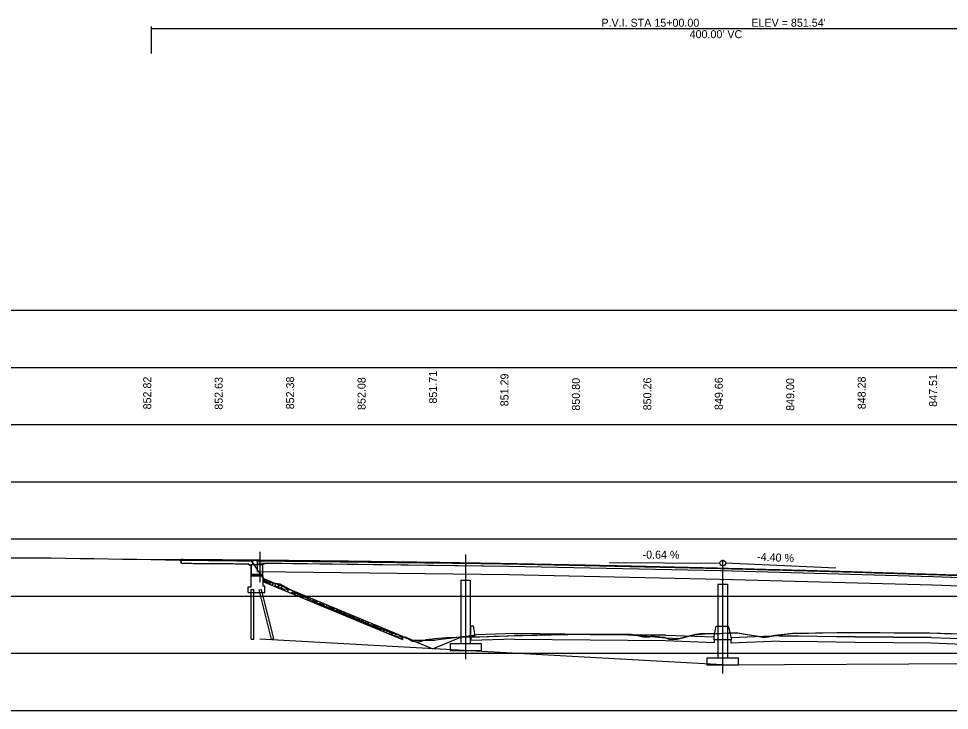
# Model space of a CAD drawing. Extents: x -434 to 1339, y -871 to 603.
# Drawn here: x 253.6 to 579.3, y -500 to -257.9 of the extents above; entities that cross this region are included whole.
import ezdxf

# ---------------------------------------------------------------- set-up
doc = ezdxf.new("R2010")
doc.units = 0
for name, color, linetype in [('BR_P_Brg_Pad_Object', 7, 'Continuous'), ('BR_P_Gen_Approach_Slab', 7, 'Continuous'), ('BR_P_Gen_Hatch', 7, 'Continuous'), ('BR_P_Gen_Slope_Protection', 7, 'Continuous'), ('BR_P_Slab_Object', 7, 'Continuous'), ('BR_P_Sub_Const_Joint', 7, 'Continuous'), ('BR_P_Sub_Object', 7, 'Continuous'), ('BR_X_Beam_Object', 7, 'Continuous'), ('BR_X_Sub_Centerline', 7, 'Continuous'), ('BR_X_Sub_Deep_Hidden', 7, 'Continuous'), ('BR_X_Sub_Deep_Object', 7, 'Continuous'), ('BR_X_Sub_Object', 7, 'Continuous'), ('GK_Cells', 7, 'Continuous'), ('PF_P_Grade_Line', 7, 'Continuous'), ('PF_P_Text', 7, 'Continuous'), ('PF_X_Ground_Line', 7, 'Continuous'), ('PV_P_EOP', 7, 'Continuous'), ('SC_Scratch1', 7, 'Continuous'), ('SC_Scratch2', 7, 'Continuous'), ('XS_P_Barrier', 7, 'Continuous'), ('XS_P_Barrier_Surface', 7, 'Continuous'), ('XS_P_Ditch_Bottom', 7, 'Continuous'), ('XS_P_Finished_Grade', 7, 'Continuous'), ('XS_P_Finished_Grade_Seeded', 7, 'Continuous'), ('XS_P_Pavt_Surface', 7, 'Continuous'), ('XS_P_Shoulder_Surface', 7, 'Continuous'), ('XS_P_Subgrade', 7, 'Continuous'), ('XS_X_Ground_Line', 7, 'Continuous')]:
    doc.layers.add(name, color=color, linetype=linetype)

msp = doc.modelspace()

# ---------------------------------------------------------------- linework, layer by layer
at = {"layer": 'BR_P_Brg_Pad_Object'}
msp.add_lwpolyline([(337.49, -452.29), (338.49, -452.29), (338.49, -452.46), (337.49, -452.46)], close=True, dxfattribs=at)
at = {"layer": 'BR_P_Gen_Approach_Slab'}
for p, q in [((310.5, -448.51), (310.5, -447.25)), ((334.45, -449.18), (333.98, -448.71)), ((334.45, -449.18), (334.95, -449.18))]:
    msp.add_line(p, q, dxfattribs=at)
msp.add_open_spline([(310.5, -448.51), (318.33, -448.57), (326.16, -448.63), (333.98, -448.71)], degree=2, dxfattribs=at)
at = {"layer": 'BR_P_Gen_Hatch'}
for p, q in [((310.5, -447.25), (310.5, -448.51)), ((333.98, -448.71), (334.45, -449.18)), ((334.45, -449.18), (334.95, -449.18)), ((334.95, -449.18), (334.95, -452.96)), ((339.09, -448.97), (340.09, -448.44)), ((339.09, -452.96), (339.09, -448.97)), ((334.95, -452.96), (339.09, -452.96))]:
    msp.add_line(p, q, dxfattribs=at)
for points in [[(340.09, -448.44), (425.16, -449.49), (499.17, -451.07), (573.52, -453.13), (641.6, -455.57)], [(339.36, -453.9), (339.09, -453.93)], [(339.31, -454.82), (339.23, -454.34), (339.53, -454), (339.6, -454)], [(340.15, -454.23), (340.26, -454.36), (340.23, -454.72), (339.89, -455.01), (339.6, -455.01), (339.31, -454.82)], [(340.11, -455.3), (340.27, -454.94), (340.64, -454.63), (340.95, -454.62), (341.22, -454.9), (341.29, -455.46), (341.2, -455.75)], [(341.58, -455.91), (341.52, -455.57), (341.82, -455.23), (342.27, -455.24), (342.55, -455.59), (342.52, -455.95), (342.25, -456.18)], [(344.59, -456.07), (344.5, -456.33), (344.15, -456.7), (343.81, -456.75), (343.5, -456.49), (343.41, -456.07), (343.45, -455.73)], [(343.44, -455.76), (343.5, -455.62)], [(344.63, -457.06), (344.54, -456.58), (344.84, -456.25), (345.01, -456.25)], [(345.42, -456.42), (345.58, -456.61), (345.54, -456.96), (345.21, -457.25), (344.92, -457.26), (344.63, -457.06)], [(345.23, -457.42), (345.63, -457.33), (345.96, -457.37)], [(345.94, -457.37), (346.46, -457.59), (346.77, -457.96), (346.77, -458.06)], [(347.09, -457.51), (347.02, -457.08)], [(347.95, -457.47), (347.68, -457.7), (347.39, -457.7), (347.09, -457.51)], [(348.06, -458.6), (347.86, -458.4), (347.8, -458.06), (348.07, -457.75), (348.44, -457.67)], [(349.46, -458.1), (349.63, -458.29), (349.63, -458.6), (349.35, -458.88), (348.87, -458.93)], [(349.44, -459.17), (349.53, -459.07), (349.97, -459.08), (350.26, -459.43), (350.25, -459.51)], [(351.11, -458.78), (351.08, -458.88), (350.73, -459.24), (350.38, -459.3), (350.08, -459.03), (349.99, -458.62), (350.02, -458.33)], [(351.06, -459.84), (351.1, -459.73), (351.47, -459.41), (351.79, -459.41), (352.06, -459.69), (352.13, -460.25), (352.12, -460.28)], [(352.39, -460.15), (352.31, -459.67), (352.56, -459.38)], [(353.34, -459.71), (353.31, -460.05), (352.97, -460.34), (352.68, -460.35), (352.39, -460.15)], [(353.13, -460.7), (353.11, -460.61), (353.38, -460.31), (353.79, -460.22), (354.13, -460.25)], [(354.11, -460.25), (354.62, -460.47), (354.93, -460.84), (354.94, -461.16), (354.73, -461.36)], [(355.36, -461.63), (355.38, -461.41)], [(355.37, -461.43), (355.6, -460.91), (355.81, -460.73)], [(356.58, -461.05), (356.62, -461.43), (356.43, -462), (356.39, -462.05)], [(356.63, -462.16), (356.58, -461.87), (356.76, -461.67), (357.03, -461.67), (357.2, -461.88), (357.18, -462.1), (356.98, -462.27), (356.91, -462.27)], [(356.64, -462.16), (356.63, -462.16)], [(358.09, -461.68), (357.89, -461.88), (357.55, -461.94), (357.25, -461.67), (357.16, -461.29)], [(358.19, -462.51), (358.1, -462.03), (358.33, -461.78)], [(359.13, -462.11), (359.1, -462.41), (358.77, -462.7), (358.48, -462.7), (358.19, -462.51)], [(359.48, -462.8), (359.4, -462.32), (359.46, -462.25)], [(358.75, -463.04), (358.89, -462.88), (359.16, -462.89), (359.33, -463.1), (359.32, -463.27)], [(360.41, -462.64), (360.4, -462.7), (360.07, -462.99), (359.78, -462.99), (359.48, -462.8)], [(359.52, -463.36), (359.76, -463.35), (359.93, -463.52)], [(360.51, -463.45), (360.43, -462.97), (360.64, -462.74)], [(361.46, -463.08), (361.43, -463.36), (361.1, -463.65), (360.81, -463.65), (360.51, -463.45)], [(360.96, -463.95), (361, -463.9), (361.42, -463.81), (361.75, -463.85)], [(361.73, -463.84), (362.25, -464.07), (362.56, -464.44), (362.56, -464.62)], [(363.67, -464), (363.64, -464.03), (363.08, -464.1), (362.51, -463.91), (362.14, -463.56), (362.11, -463.35)], [(362.87, -464.74), (362.85, -464.67), (363.15, -464.34), (363.6, -464.35), (363.89, -464.7), (363.85, -465.06), (363.78, -465.12)], [(363.93, -464.34), (363.88, -464.08)], [(363.92, -465.18), (364.04, -465.06), (364.3, -465.06), (364.48, -465.27), (364.46, -465.41)], [(364.44, -464.31), (364.27, -464.45), (364.1, -464.46), (363.93, -464.34)], [(364.83, -464.91), (364.78, -464.62), (364.88, -464.5)], [(364.8, -465.55), (365.02, -465.29), (365.44, -465.2), (365.78, -465.24)], [(365.39, -464.71), (365.38, -464.85), (365.18, -465.02), (365, -465.02), (364.83, -464.91)], [(365.75, -465.23), (366.27, -465.46), (366.58, -465.83), (366.59, -466.14), (366.48, -466.25)], [(366.45, -465.36), (366.41, -465.13)], [(367.17, -465.45), (367.04, -465.56), (366.75, -465.56), (366.46, -465.36)], [(367.29, -466.02), (367.24, -465.73), (367.41, -465.55)], [(367.85, -465.73), (367.86, -465.75), (367.84, -465.96), (367.64, -466.14), (367.47, -466.14), (367.29, -466.02)], [(366.58, -466.29), (366.84, -466.07), (367.15, -466.06), (367.42, -466.34), (367.46, -466.65)], [(369.1, -466.25), (369.08, -466.3), (368.73, -466.66), (368.39, -466.72), (368.08, -466.46), (367.99, -466.04), (368.02, -465.8)], [(368.91, -467.25), (368.89, -467.13), (369.19, -466.8), (369.63, -466.81), (369.92, -467.16), (369.89, -467.52), (369.78, -467.61)], [(370.23, -467.51), (370.18, -467.22), (370.36, -467.02), (370.63, -467.03), (370.8, -467.24), (370.78, -467.45), (370.58, -467.62), (370.4, -467.63), (370.23, -467.51)], [(370.31, -467.84), (370.56, -467.84), (370.68, -467.99)], [(371.01, -468.09), (370.93, -467.61), (371.23, -467.27), (371.59, -467.28)], [(371.15, -468.18), (371.01, -468.09)], [(371.72, -467.33), (371.96, -467.63), (371.93, -467.99), (371.59, -468.28), (371.4, -468.28)], [(371.95, -468.52), (371.94, -468.45), (372.24, -468.11), (372.69, -468.12), (372.98, -468.47), (372.94, -468.83), (372.87, -468.9)], [(373.03, -467.88), (372.88, -467.91), (372.68, -467.74)], [(373.03, -468.96), (373.04, -468.93), (373.41, -468.62), (373.73, -468.61), (374, -468.89), (374.06, -469.39)], [(373.71, -468.39), (373.67, -468.15)], [(374.22, -468.37), (374.06, -468.51), (373.89, -468.51), (373.71, -468.39)], [(374.32, -469.02), (374.23, -468.54), (374.34, -468.42)], [(375.25, -468.8), (375.23, -468.93), (374.9, -469.22), (374.61, -469.22), (374.32, -469.02)], [(374.75, -469.68), (375.03, -469.36), (375.48, -469.37), (375.77, -469.72), (375.74, -470.08), (375.73, -470.08)], [(376.01, -470.2), (375.96, -469.98), (376, -469.65)], [(375.99, -469.67), (376.2, -469.2)], [(377.24, -469.63), (377.24, -469.67), (377.05, -470.24), (376.78, -470.52)], [(377.48, -470.81), (377.76, -470.5), (378.2, -470.51), (378.49, -470.86), (378.46, -471.22), (378.46, -471.22)], [(379.37, -470.51), (378.87, -470.58), (378.3, -470.39), (377.93, -470.03), (377.91, -469.91)], [(379.25, -471.44), (379.17, -470.96), (379.47, -470.62), (379.65, -470.63)], [(380.05, -470.79), (380.2, -470.98), (380.17, -471.34), (379.84, -471.63), (379.55, -471.64), (379.25, -471.44)], [(380.07, -471.89), (380.21, -471.56), (380.58, -471.25), (380.89, -471.25), (381.17, -471.53), (381.23, -472.09), (381.15, -472.33)], [(381.51, -472.49), (381.46, -472.19), (381.76, -471.86), (382.21, -471.87), (382.5, -472.22), (382.46, -472.57), (382.23, -472.78)], [(382.78, -471.93), (382.32, -471.78), (382.26, -471.71)], [(383.39, -472.38), (383.46, -472.21)], [(384.54, -472.66), (384.45, -472.96), (384.09, -473.32), (383.75, -473.38), (383.45, -473.11), (383.35, -472.69), (383.39, -472.36)], [(384.57, -473.68), (384.48, -473.2), (384.78, -472.87), (385.06, -472.87)], [(384.84, -473.87), (384.57, -473.68)], [(385.32, -472.98), (385.52, -473.23), (385.49, -473.59), (385.15, -473.88), (384.87, -473.88)], [(385.23, -474.03), (385.57, -473.96), (385.91, -473.99)], [(385.88, -473.99), (386.4, -474.21), (386.71, -474.58), (386.71, -474.64)], [(387.04, -474.13), (386.96, -473.66)], [(387.92, -474.06), (387.62, -474.32), (387.33, -474.33), (387.04, -474.13)], [(387.93, -475.15), (387.8, -475.03), (387.74, -474.68), (387.96, -474.44)]]:
    msp.add_lwpolyline(points, dxfattribs=at)
msp.add_spline([(671.19, -456.03), (668, -455.9), (660, -455.58), (652, -455.26), (644, -454.94), (636, -454.64), (628, -454.34), (620, -454.04), (612, -453.75), (604, -453.47), (596, -453.19), (588, -452.92), (580, -452.66), (572, -452.4), (564, -452.15), (556, -451.9), (548, -451.66), (540, -451.42), (532, -451.19), (524, -450.97), (516, -450.76), (508, -450.54), (500, -450.34), (492, -450.14), (484, -449.95), (476, -449.76), (468, -449.58), (460, -449.41), (452, -449.24), (444, -449.08), (436, -448.92), (428, -448.77), (420, -448.62), (412, -448.49), (404, -448.35), (396, -448.23), (388, -448.11), (380, -447.99), (372, -447.88), (364, -447.78), (356, -447.69), (348, -447.6), (340, -447.51), (332, -447.43), (324, -447.36), (316, -447.29), (310.5, -447.25)], degree=3, dxfattribs=at)
msp.add_open_spline([(310.5, -448.51), (318.33, -448.57), (326.16, -448.63), (333.98, -448.71)], degree=2, dxfattribs=at)
at = {"layer": 'BR_P_Gen_Slope_Protection'}
for p, q in [((339.09, -453.79), (387.96, -474.08)), ((339.09, -454.87), (387.96, -475.16)), ((387.96, -474.08), (387.96, -475.16))]:
    msp.add_line(p, q, dxfattribs=at)
at = {"layer": 'BR_P_Slab_Object'}
msp.add_lwpolyline([(340.09, -448.44), (425.16, -449.49), (499.17, -451.07), (573.52, -453.13), (641.6, -455.57)], dxfattribs=at)
at = {"layer": 'BR_P_Sub_Const_Joint'}
msp.add_line((335.5, -448.97), (339.09, -448.97), dxfattribs=at)
at = {"layer": 'BR_P_Sub_Object'}
for p, q in [((334.95, -452.29), (334.95, -448.97)), ((334.95, -448.97), (335.5, -448.97)), ((335.5, -448.97), (335.5, -447.47)), ((339.09, -448.97), (340.09, -448.44)), ((339.09, -452.29), (339.09, -448.97)), ((334.95, -452.29), (339.09, -452.29)), ((334.95, -452.46), (339.09, -452.46)), ((334.95, -452.96), (334.95, -452.46)), ((339.09, -452.96), (339.09, -452.46)), ((334.95, -452.96), (339.09, -452.96))]:
    msp.add_line(p, q, dxfattribs=at)
at = {"layer": 'BR_X_Beam_Object'}
msp.add_line((337.13, -447.65), (337.13, -451.39), dxfattribs=at)
for points in [[(337.13, -448.4), (425.16, -449.49), (499.17, -451.07), (573.52, -453.13), (644.55, -455.67)], [(337.13, -451.39), (425.11, -452.48), (499.1, -454.06), (573.42, -456.12), (644.55, -458.66)]]:
    msp.add_lwpolyline(points, dxfattribs=at)
at = {"layer": 'BR_X_Sub_Centerline'}
for p, q in [((337.99, -444.5), (337.99, -455.19)), ((409.99, -445.45), (409.99, -482.08)), ((499.95, -447.34), (499.95, -487.08))]:
    msp.add_line(p, q, dxfattribs=at)
at = {"layer": 'BR_X_Sub_Deep_Hidden'}
for p, q in [((335.03, -457.74), (335.87, -457.74)), ((335.03, -458.74), (335.03, -457.74)), ((335.87, -458.74), (335.87, -457.74)), ((337.79, -457.84), (338.6, -457.64)), ((338.02, -458.74), (337.79, -457.84)), ((338.88, -458.74), (338.6, -457.64))]:
    msp.add_line(p, q, dxfattribs=at)
at = {"layer": 'BR_X_Sub_Deep_Object'}
for p, q in [((335.03, -475.08), (335.03, -458.74)), ((335.87, -475.08), (335.87, -458.74)), ((342.1, -475.08), (338.02, -458.74)), ((342.91, -474.88), (338.88, -458.74)), ((335.03, -475.08), (335.87, -475.08)), ((342.1, -475.08), (342.91, -474.88))]:
    msp.add_line(p, q, dxfattribs=at)
at = {"layer": 'BR_X_Sub_Object'}
for p, q in [((334.95, -456.74), (334.95, -452.96)), ((339.09, -452.96), (339.09, -456.49)), ((408.33, -454.46), (411.65, -454.46)), ((408.33, -454.46), (408.33, -476.58)), ((411.65, -454.46), (411.65, -476.58)), ((498.22, -455.81), (501.68, -455.81)), ((498.22, -455.81), (498.22, -481.58)), ((501.68, -455.81), (501.68, -481.58)), ((333.95, -458.74), (333.95, -456.74)), ((333.95, -456.74), (334.95, -456.74)), ((333.95, -458.74), (339.7, -458.74)), ((339.7, -456.49), (339.09, -456.49)), ((339.7, -458.74), (339.7, -456.49)), ((404.58, -476.58), (415.4, -476.58)), ((404.58, -476.58), (404.58, -479.08)), ((415.4, -476.58), (415.4, -479.08)), ((404.58, -479.08), (415.4, -479.08)), ((494.47, -481.58), (505.43, -481.58)), ((494.47, -481.58), (494.47, -484.08)), ((505.43, -481.58), (505.43, -484.08)), ((494.47, -484.08), (505.43, -484.08))]:
    msp.add_line(p, q, dxfattribs=at)
at = {"layer": 'GK_Cells'}
msp.add_line((0, -500), (1100, -500), dxfattribs=at)
at = {"layer": 'PF_P_Grade_Line'}
msp.add_spline([(300, -447.18), (308, -447.23), (316, -447.29), (324, -447.36), (332, -447.43), (340, -447.51), (348, -447.6), (356, -447.69), (364, -447.78), (372, -447.88), (380, -447.99), (388, -448.11), (396, -448.23), (404, -448.35), (412, -448.49), (420, -448.62), (428, -448.77), (436, -448.92), (444, -449.08), (452, -449.24), (460, -449.41), (468, -449.58), (476, -449.76), (484, -449.95), (492, -450.14), (500, -450.34), (508, -450.54), (516, -450.76), (524, -450.97), (532, -451.19), (540, -451.42), (548, -451.66), (556, -451.9), (564, -452.15), (572, -452.4), (580, -452.66), (588, -452.92), (596, -453.19), (604, -453.47), (612, -453.75), (620, -454.04), (628, -454.34), (636, -454.64), (644, -454.94), (652, -455.26), (660, -455.58), (668, -455.9), (676, -456.23), (684, -456.57), (692, -456.91), (700, -457.26)], degree=3, dxfattribs=at)
at = {"layer": 'PF_P_Text'}
for p, q in [((300, -260.67), (300, -270.09)), ((300, -261.37), (700, -261.37)), ((460.4, -448.21), (499, -448.45)), ((539.56, -450.2), (501, -448.5))]:
    msp.add_line(p, q, dxfattribs=at)
msp.add_circle((500, -448.46), 1, dxfattribs=at)
at = {"layer": 'PF_X_Ground_Line'}
msp.add_lwpolyline([(336.84, -447.65), (425.17, -448.74), (499.19, -450.32), (573.54, -452.38), (645.15, -454.94)], dxfattribs=at)
at = {"layer": 'PV_P_EOP'}
for p, q in [((453.55, -473.42), (427.06, -473.14)), ((466.8, -473.56), (453.55, -473.42)), ((480.06, -473.7), (466.8, -473.56)), ((533.1, -474.09), (519.83, -473.94)), ((546.37, -474.24), (533.1, -474.09)), ((572.91, -474.53), (546.37, -474.24))]:
    msp.add_line(p, q, dxfattribs=at)
at = {"layer": 'SC_Scratch1'}
for p, q in [((0, -360), (1339.17, -360)), ((0, -380), (1339.17, -380)), ((0, -400), (1339.17, -400)), ((0, -420), (1339.17, -420)), ((0, -440), (1339.17, -440)), ((0, -460), (1339.17, -460)), ((499.95, -484.08), (337.99, -475.08)), ((0, -480), (1339.17, -480)), ((499.95, -484.08), (643.7, -483.28)), ((0, -500), (1339.17, -500))]:
    msp.add_line(p, q, dxfattribs=at)
at = {"layer": 'SC_Scratch2'}
for points in [[(250, -446.57), (255, -446.59), (260, -446.61), (265, -446.63), (270, -446.71), (275, -446.8), (280, -446.88), (285, -446.97), (290, -447.06), (295, -447.14), (300, -447.23), (305, -447.31), (310, -447.4), (315, -447.49), (320, -447.57), (325, -447.6), (330, -447.65), (335, -447.72), (340, -455.02), (345, -455.67), (350, -458.5), (355, -461.02), (360, -463.23), (365, -465.34), (370, -467.31), (375, -469.42), (380, -471.33), (385, -473), (396.29, -477.54), (397.49, -478.04), (398.45, -478.43), (408.33, -474.33), (410, -474.26), (415, -474.23), (420, -474.05), (425, -473.88), (430, -473.76), (435, -473.66), (440, -473.56), (445, -473.46), (450, -473.36), (455, -473.3), (460, -473.29), (465, -473.28), (470, -473.78), (475, -474.11), (480, -474.59), (485, -474.8), (490, -473.51), (495, -473.1), (500, -473.01)], [(387.96, -474.19), (396.29, -477.54), (397.49, -478.04), (398.45, -478.43), (408.33, -474.33)], [(500, -473.01), (505, -472.81), (510, -473.69), (515, -474.42), (520, -473.55), (525, -473.03), (530, -473), (535, -472.87), (540, -472.8), (545, -472.73), (550, -472.76), (555, -472.79), (560, -472.83), (565, -472.86), (570, -472.9), (575, -473), (580, -473.16)]]:
    msp.add_lwpolyline(points, dxfattribs=at)
at = {"layer": 'XS_P_Barrier'}
for p, q in [((497, -475.31), (497, -474.31)), ((502.9, -475.31), (497, -475.31)), ((502.9, -474.56), (502.9, -475.31))]:
    msp.add_line(p, q, dxfattribs=at)
at = {"layer": 'XS_P_Barrier_Surface'}
for p, q in [((411.83, -470.38), (411.79, -470.42)), ((411.79, -473.93), (411.79, -470.42)), ((411.83, -470.38), (412.58, -470.38)), ((411.83, -470.38), (412.58, -470.38)), ((412.58, -470.38), (412.63, -470.42)), ((412.63, -470.42), (413.29, -473.93)), ((497, -474.06), (497.74, -470.56)), ((497.74, -470.56), (498.29, -470.56)), ((498.29, -470.56), (501.61, -470.56)), ((501.61, -470.56), (501.61, -470.81)), ((502.16, -470.81), (501.61, -470.81)), ((502.9, -474.31), (502.16, -470.81)), ((413.29, -473.93), (411.79, -473.93)), ((497, -474.31), (497, -474.06)), ((502.9, -474.56), (502.9, -474.31))]:
    msp.add_line(p, q, dxfattribs=at)
at = {"layer": 'XS_P_Ditch_Bottom'}
msp.add_line((391.35, -475.47), (399.51, -475.47), dxfattribs=at)
at = {"layer": 'XS_P_Finished_Grade'}
for p, q in [((391.35, -475.47), (388.95, -474.36)), ((411.79, -473.93), (399.51, -475.47))]:
    msp.add_line(p, q, dxfattribs=at)
at = {"layer": 'XS_P_Finished_Grade_Seeded'}
msp.add_line((413.82, -473.62), (411.79, -473.93), dxfattribs=at)
at = {"layer": 'XS_P_Pavt_Surface'}
for p, q in [((427.06, -473.14), (453.55, -473.39)), ((453.55, -473.39), (466.8, -473.52)), ((466.8, -473.52), (480.06, -473.65)), ((519.83, -473.94), (533.1, -474.08)), ((533.1, -474.08), (546.37, -474.21)), ((546.37, -474.21), (572.91, -474.48))]:
    msp.add_line(p, q, dxfattribs=at)
at = {"layer": 'XS_P_Shoulder_Surface'}
for p, q in [((427.06, -473.14), (413.82, -473.62)), ((480.06, -473.7), (497, -474.31)), ((519.83, -473.94), (502.9, -474.56)), ((572.91, -474.53), (586.19, -475.01))]:
    msp.add_line(p, q, dxfattribs=at)
at = {"layer": 'XS_P_Subgrade'}
for p, q in [((411.79, -473.93), (411.79, -475.57)), ((427.06, -475.02), (411.79, -475.57)), ((427.06, -475.02), (453.55, -475.27)), ((453.55, -475.27), (466.8, -475.4)), ((466.8, -475.4), (480.06, -475.52)), ((497, -475.31), (497, -476.19)), ((502.9, -475.31), (497, -475.31)), ((502.9, -476.43), (502.9, -475.31)), ((480.06, -475.58), (497, -476.19)), ((519.83, -475.82), (502.9, -476.43)), ((519.83, -475.82), (533.1, -475.95)), ((533.1, -475.95), (546.37, -476.09)), ((546.37, -476.09), (572.91, -476.35)), ((572.91, -476.41), (588.22, -476.96))]:
    msp.add_line(p, q, dxfattribs=at)
at = {"layer": 'XS_X_Ground_Line'}
for p, q in [((360.01, -463.27), (365.04, -465.39)), ((365.04, -465.39), (368.7, -466.8)), ((368.7, -466.8), (374.84, -469.38)), ((374.84, -469.38), (379.29, -471.11)), ((379.29, -471.11), (383.72, -472.59)), ((383.72, -472.59), (389.57, -474.57)), ((389.57, -474.57), (391.26, -475.79)), ((393.7, -476.01), (396.27, -475.15)), ((396.27, -475.15), (399.2, -474.83)), ((399.2, -474.83), (403.18, -474.54)), ((403.18, -474.54), (410.26, -474.24)), ((410.26, -474.24), (411.03, -474.23)), ((411.03, -474.23), (413.45, -474.21)), ((413.45, -474.21), (414.02, -474.21)), ((414.02, -474.21), (414.61, -474.27)), ((414.61, -474.27), (421.55, -473.99)), ((421.55, -473.99), (427.06, -473.8)), ((427.06, -473.8), (452.08, -473.31)), ((452.08, -473.31), (452.82, -473.29)), ((452.82, -473.29), (460.62, -473.28)), ((460.62, -473.28), (465.71, -473.28)), ((465.71, -473.28), (467.91, -473.36)), ((467.91, -473.36), (472.24, -474.25)), ((472.24, -474.25), (474.46, -474.26)), ((474.46, -474.26), (475, -474.07)), ((475, -474.07), (475.64, -473.96)), ((475.64, -473.96), (476.85, -474.1)), ((476.85, -474.1), (477.51, -474.18)), ((477.51, -474.18), (477.85, -474.22)), ((477.85, -474.22), (479.59, -474.42)), ((479.59, -474.42), (481.32, -475.23)), ((481.32, -475.23), (482.22, -475.1)), ((482.22, -475.1), (483.71, -475.16)), ((483.71, -475.16), (486.74, -474.25)), ((486.74, -474.25), (490.44, -473.38)), ((490.44, -473.38), (492.2, -473.11)), ((492.2, -473.11), (494.46, -473.1)), ((494.46, -473.1), (499.18, -473.04)), ((499.18, -473.04), (499.94, -473)), ((499.94, -473), (501.63, -472.91)), ((501.63, -472.91), (504.65, -472.75)), ((504.65, -472.75), (507.8, -473.32)), ((507.8, -473.32), (509.5, -473.6)), ((509.5, -473.6), (512.15, -474.08)), ((512.15, -474.08), (514.42, -474.5)), ((514.42, -474.5), (515.94, -474.23)), ((515.94, -474.23), (518.25, -473.65)), ((518.25, -473.65), (520.58, -473.49)), ((520.58, -473.49), (524.44, -472.99)), ((524.44, -472.99), (525.1, -473.02)), ((525.1, -473.02), (527.08, -473.09)), ((527.08, -473.09), (529.48, -473)), ((529.48, -473), (532.47, -472.9)), ((532.47, -472.9), (542.6, -472.75)), ((542.6, -472.75), (545.13, -472.72)), ((545.13, -472.72), (565.2, -472.85)), ((565.2, -472.85), (572.45, -472.9)), ((572.45, -472.9), (583.54, -473.26)), ((391.26, -475.79), (392.8, -476.01)), ((392.8, -476.01), (393.7, -476.01))]:
    msp.add_line(p, q, dxfattribs=at)

# ---------------------------------------------------------------- texts
at = {"layer": 'PF_P_Text'}
for s, p in [('P.V.I. STA 15+00.00', (457.54, -260.77)), ("ELEV = 851.54'", (510, -260.77)), ("400.00' VC", (488.4, -264.77))]:
    msp.add_text(s, height=2.8, dxfattribs=at).set_placement(p)
for s, rotation, p in [('852.82', 90, (300, -394.67)), ('852.63', 90, (325, -394.78)), ('852.38', 90, (350, -394.64)), ('852.08', 90, (375, -394.86)), ('851.71', 90, (400, -392.63)), ('851.29', 90, (425, -393.58)), ('850.80', 90, (450, -395.11)), ('850.26', 90, (475, -395)), ('849.66', 90, (500, -394.89)), ('849.00', 90, (525, -395.17)), ('848.28', 90, (550, -394.62)), ('847.51', 90, (575, -393.76)), ('-0.64 %', 359.6333, (471.92, -446.88)), ('-4.40 %', 357.4806, (511.97, -447.59))]:
    msp.add_text(s, height=2.8, rotation=rotation, dxfattribs=at).set_placement(p)

doc.saveas('drawing.dxf')
